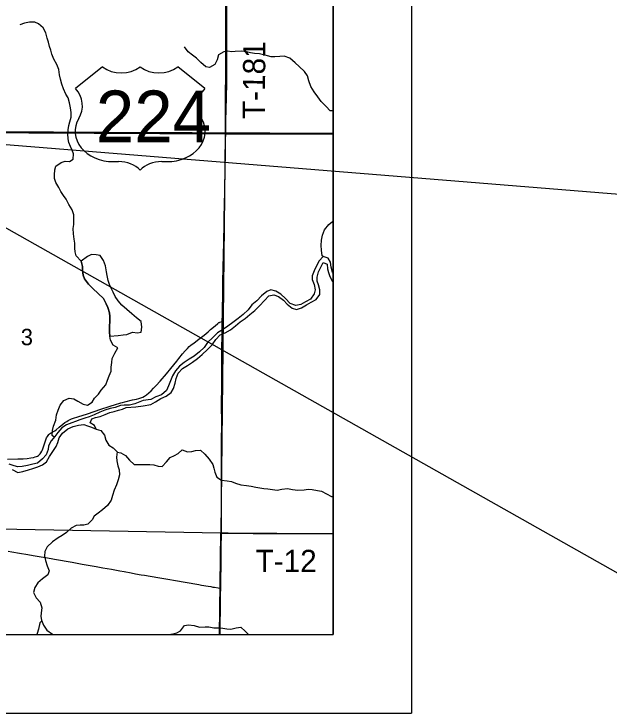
# Model space of a CAD drawing. Extents: x 0 to 34, y 0 to 22.
# Drawn here: x 8.493 to 9.252, y 14 to 14.891 of the extents above; entities that cross this region are included whole.
import ezdxf

# ---------------------------------------------------------------- set-up
doc = ezdxf.new("R2010")
doc.units = 0
for name, color, linetype in [('GM_X_Corporation', 7, 'Continuous'), ('GM_X_County_Road', 7, 'Continuous'), ('GM_X_Major_River', 7, 'Continuous'), ('GM_X_Minor_Lake', 7, 'Continuous'), ('GM_X_Minor_River', 7, 'Continuous'), ('GM_X_Section_Text', 7, 'Continuous'), ('GM_X_Township_Road', 7, 'Continuous'), ('GM_X_Township_Road_Text', 7, 'Continuous'), ('GM_X_US_Location', 7, 'Continuous'), ('GM_X_US_Route', 7, 'Continuous'), ('GM_X_US_Shield', 7, 'Continuous'), ('SH_Data', 7, 'Continuous'), ('SH_Text', 7, 'Continuous')]:
    doc.layers.add(name, color=color, linetype=linetype)

msp = doc.modelspace()

# ---------------------------------------------------------------- linework, layer by layer
at = {"layer": 'GM_X_Corporation'}
for points in [[(2.1, 20.71973), (2.1, 14.1), (8.9, 14.1), (8.9, 20.77204)], [(8.46983, 14.7408), (8.50534, 14.74055), (8.54325, 14.7406), (8.57401, 14.74045), (8.61034, 14.74013), (8.6641, 14.74008), (8.68834, 14.74), (8.72034, 14.73988), (8.76199, 14.73959), (8.76305, 14.73959), (8.79524, 14.73942), (8.81918, 14.73932), (8.86703, 14.73918), (8.89873, 14.73911), (8.9, 14.7391), (8.9, 17.77596)], [(6.729, 14.1), (8.9, 14.1), (8.9, 14.7391), (8.89873, 14.73911), (8.86703, 14.73918), (8.81918, 14.73932), (8.79524, 14.73942), (8.76305, 14.73959), (8.76199, 14.73959), (8.72034, 14.73988), (8.68834, 14.74), (8.6641, 14.74008), (8.61034, 14.74013), (8.57401, 14.74045), (8.54325, 14.7406), (8.50534, 14.74055), (8.46983, 14.7408)]]:
    msp.add_lwpolyline(points, dxfattribs=at)
for points in [[(8.26181, 15.24197), (8.76425, 15.24174), (8.76242, 14.73868), (8.2606, 14.74118)], [(8.9, 14.73823), (8.9, 15.24104), (8.76425, 15.24174), (8.76242, 14.73868)], [(8.2606, 14.74118), (8.76242, 14.73868), (8.75677, 14.2292), (8.25919, 14.2385)], [(8.9, 14.22852), (8.9, 14.73823), (8.76242, 14.73868), (8.75677, 14.2292)], [(8.25754, 14.1), (8.75508, 14.1), (8.75677, 14.2292), (8.25919, 14.2385)], [(8.75508, 14.1), (8.9, 14.1), (8.9, 14.22852), (8.75677, 14.2292)]]:
    msp.add_lwpolyline(points, close=True, dxfattribs=at)
at = {"layer": 'GM_X_County_Road'}
for points in [[(8.75873, 14.49937), (8.75897, 14.50831), (8.75916, 14.51701), (8.75916, 14.52012), (8.75924, 14.52882), (8.75921, 14.53472), (8.75931, 14.53968), (8.75947, 14.54558), (8.75947, 14.55056), (8.75952, 14.55615), (8.75966, 14.56142), (8.75988, 14.57105), (8.76008, 14.58131), (8.76059, 14.60306), (8.76092, 14.62139), (8.7611, 14.63164), (8.76146, 14.64904), (8.76178, 14.66489), (8.7624, 14.69627), (8.76269, 14.71088), (8.76277, 14.71771), (8.76282, 14.72175), (8.76287, 14.72547), (8.76293, 14.73011), (8.76316, 14.73931)], [(8.75757, 14.22962), (8.75761, 14.23733), (8.75766, 14.25162), (8.75778, 14.26561), (8.75777, 14.28457), (8.75775, 14.30135), (8.75779, 14.31875), (8.75781, 14.34082), (8.75794, 14.37438), (8.75785, 14.38775), (8.75785, 14.39707), (8.75792, 14.41354), (8.75794, 14.42442), (8.75804, 14.44182), (8.75802, 14.45053), (8.7581, 14.46885), (8.75839, 14.47786), (8.75854, 14.4875), (8.75866, 14.49682), (8.75873, 14.49937)], [(8.75675, 14.15906), (8.75682, 14.16367), (8.75693, 14.1702), (8.75719, 14.18853), (8.75738, 14.20531), (8.75744, 14.21433), (8.75754, 14.22458), (8.75757, 14.22962)], [(8.7559, 14.1), (8.75609, 14.11305), (8.75618, 14.11988), (8.75624, 14.12547), (8.75647, 14.13913), (8.75655, 14.14503), (8.75663, 14.15093), (8.75675, 14.15906)]]:
    msp.add_lwpolyline(points, dxfattribs=at)
at = {"layer": 'GM_X_Major_River'}
for points in [[(8.9, 14.56088), (8.89935, 14.56216), (8.89768, 14.56843), (8.89695, 14.57507), (8.89394, 14.58021), (8.88731, 14.58214), (8.88235, 14.57685), (8.8791, 14.57023), (8.87603, 14.56398), (8.87334, 14.55754), (8.87351, 14.5528), (8.87614, 14.54652), (8.87724, 14.53969), (8.87608, 14.53438), (8.87111, 14.52795), (8.86503, 14.52438), (8.85875, 14.5208), (8.85248, 14.5195), (8.84548, 14.52239), (8.83925, 14.52868), (8.83359, 14.53402), (8.82716, 14.53785), (8.82053, 14.53978), (8.8154, 14.53772), (8.80873, 14.53206), (8.80282, 14.52582), (8.79634, 14.52035), (8.79157, 14.5143), (8.78528, 14.50826), (8.77881, 14.50317), (8.77196, 14.49789), (8.76586, 14.49337), (8.75901, 14.48847), (8.75274, 14.48489), (8.74645, 14.47904), (8.73997, 14.47243), (8.73538, 14.466), (8.72948, 14.46053), (8.72281, 14.45525), (8.71653, 14.4513), (8.71025, 14.44696), (8.70416, 14.44244), (8.69882, 14.43639), (8.69518, 14.42996), (8.6925, 14.42371), (8.69019, 14.41746), (8.68732, 14.4114), (8.68122, 14.40574), (8.67381, 14.40331), (8.66753, 14.39993), (8.65778, 14.39837)], [(8.65775, 14.39182), (8.66769, 14.39329), (8.67359, 14.39686), (8.68044, 14.40119), (8.68728, 14.404), (8.69337, 14.40891), (8.69624, 14.41383), (8.69836, 14.42046), (8.69972, 14.42671), (8.70241, 14.43353), (8.70813, 14.43919), (8.71441, 14.44334), (8.72069, 14.44729), (8.72716, 14.452), (8.73287, 14.45729), (8.73992, 14.46351), (8.74564, 14.46975), (8.75042, 14.47618), (8.75595, 14.48222), (8.76241, 14.48466), (8.76907, 14.4888), (8.77554, 14.49389), (8.78164, 14.49898), (8.78792, 14.50331), (8.79401, 14.50803), (8.80029, 14.51331), (8.80639, 14.51916), (8.81268, 14.52615), (8.81821, 14.5322), (8.82467, 14.53331), (8.83054, 14.53138), (8.83696, 14.52641), (8.84168, 14.52146), (8.84773, 14.51611), (8.8536, 14.51475), (8.85968, 14.51681), (8.86614, 14.52039), (8.87223, 14.52377), (8.87832, 14.52754), (8.88328, 14.53358), (8.88312, 14.53966), (8.88145, 14.54612), (8.87976, 14.55087), (8.8796, 14.55599), (8.88133, 14.56244), (8.88459, 14.56849), (8.88746, 14.57455), (8.89238, 14.57244), (8.89311, 14.56636), (8.89423, 14.56161), (8.8961, 14.55686), (8.89948, 14.55039), (8.9, 14.54989)], [(8.65778, 14.39837), (8.64695, 14.39428), (8.64049, 14.39279), (8.63346, 14.39263), (8.62871, 14.39208), (8.62206, 14.38964), (8.61579, 14.38834), (8.60895, 14.38609), (8.6023, 14.38365), (8.59526, 14.38007), (8.58899, 14.37764), (8.58348, 14.37595), (8.57701, 14.37389), (8.5715, 14.37183), (8.56675, 14.37014), (8.56009, 14.36751), (8.55381, 14.36375), (8.54904, 14.35769), (8.54485, 14.35278), (8.54046, 14.34711), (8.53682, 14.34067), (8.53642, 14.33593), (8.53411, 14.3293), (8.52916, 14.32401), (8.52306, 14.31872), (8.51679, 14.31723), (8.50995, 14.31555), (8.50311, 14.31444), (8.49799, 14.31389), (8.49325, 14.31543), (8.48661, 14.31717)], [(8.49076, 14.3107), (8.49777, 14.30668), (8.50422, 14.3078), (8.51125, 14.31004), (8.51696, 14.31173), (8.52323, 14.31416), (8.52931, 14.31642), (8.53426, 14.32019), (8.53809, 14.327), (8.54344, 14.33495), (8.54669, 14.33987), (8.5488, 14.34498), (8.55034, 14.35086), (8.55473, 14.3571), (8.56178, 14.36257), (8.56825, 14.36539), (8.57509, 14.36726), (8.58192, 14.3678), (8.58666, 14.36645), (8.59159, 14.36434), (8.59765, 14.36185), (8.59577, 14.3666), (8.59009, 14.37023), (8.59201, 14.37535), (8.59695, 14.37684), (8.60284, 14.37834), (8.60931, 14.38059), (8.61539, 14.3834), (8.62052, 14.38452), (8.62641, 14.38639), (8.63135, 14.3877), (8.63611, 14.38958), (8.64826, 14.39066), (8.65775, 14.39182)]]:
    msp.add_lwpolyline(points, dxfattribs=at)
at = {"layer": 'GM_X_Minor_Lake'}
for points in [[(8.61506, 14.48075), (8.62588, 14.48146), (8.63233, 14.48219), (8.63708, 14.48274), (8.64412, 14.48556), (8.65037, 14.48477), (8.65531, 14.4857), (8.6561, 14.49215), (8.65499, 14.49917), (8.64913, 14.50394), (8.64308, 14.50928), (8.63703, 14.51443), (8.6306, 14.52015), (8.62569, 14.52567), (8.62211, 14.531), (8.61928, 14.53689), (8.61703, 14.54184), (8.61477, 14.54659), (8.61309, 14.55153), (8.6116, 14.55799), (8.61086, 14.56274), (8.60956, 14.57033), (8.60712, 14.57699), (8.60297, 14.58327), (8.59766, 14.58443), (8.59197, 14.58464), (8.58665, 14.58239), (8.57846, 14.57635)], [(8.57846, 14.57635), (8.58014, 14.56951), (8.58012, 14.56458), (8.58104, 14.5585), (8.58292, 14.55375), (8.58782, 14.54709), (8.59368, 14.54137), (8.60049, 14.53508), (8.60691, 14.5286), (8.61068, 14.52194), (8.61275, 14.517), (8.61462, 14.51054), (8.61516, 14.5056), (8.61514, 14.50048), (8.61473, 14.49194), (8.61489, 14.48549), (8.61506, 14.48075)]]:
    msp.add_lwpolyline(points, dxfattribs=at)
at = {"layer": 'GM_X_Minor_River'}
for points in [[(8.52434, 14.87907), (8.51941, 14.88118), (8.51277, 14.88102), (8.50631, 14.87972), (8.50023, 14.87785)], [(8.5442, 14.35194), (8.54162, 14.35393), (8.54222, 14.36038), (8.54319, 14.36569), (8.54607, 14.37346), (8.54724, 14.38009), (8.54917, 14.38634), (8.55166, 14.39259), (8.55643, 14.39865), (8.56309, 14.40146), (8.56935, 14.40087), (8.57446, 14.39781), (8.58128, 14.39399), (8.58658, 14.39245), (8.59248, 14.39622), (8.59554, 14.4017), (8.60069, 14.40643), (8.60413, 14.41153), (8.61023, 14.41834), (8.61235, 14.42459), (8.61446, 14.4299), (8.61676, 14.43615), (8.61697, 14.44089), (8.61776, 14.44696), (8.61816, 14.45227), (8.62161, 14.45909), (8.62543, 14.46571), (8.61937, 14.46915), (8.61598, 14.47543), (8.61506, 14.48075), (8.61489, 14.48549), (8.61473, 14.49194), (8.61514, 14.50048), (8.61516, 14.5056), (8.61462, 14.51054), (8.61275, 14.517), (8.61068, 14.52194), (8.60691, 14.5286), (8.60049, 14.53508), (8.59368, 14.54137), (8.58782, 14.54709), (8.58292, 14.55375), (8.58104, 14.5585), (8.58012, 14.56458), (8.58014, 14.56951), (8.57846, 14.57635), (8.57242, 14.58321), (8.57092, 14.58815), (8.57056, 14.59289), (8.5704, 14.59934), (8.56947, 14.60447), (8.56874, 14.61112), (8.56858, 14.61776), (8.56917, 14.62288), (8.56939, 14.62876), (8.56922, 14.63522), (8.56716, 14.64168), (8.56283, 14.64834), (8.55944, 14.65537), (8.55624, 14.66013), (8.55284, 14.66508), (8.55021, 14.67021), (8.54625, 14.67649), (8.54475, 14.68162), (8.54477, 14.68656), (8.54499, 14.69263), (8.54634, 14.69737), (8.553, 14.70208), (8.55813, 14.70377), (8.56363, 14.70355), (8.56839, 14.70619), (8.56899, 14.71302), (8.5673, 14.71777), (8.56504, 14.72253), (8.56298, 14.72747), (8.56186, 14.73222), (8.56151, 14.73848), (8.56191, 14.7436), (8.56269, 14.74929), (8.56404, 14.75403), (8.56577, 14.75972), (8.5658, 14.76598), (8.56487, 14.77187), (8.56376, 14.77832), (8.56208, 14.78459), (8.55907, 14.78935), (8.55587, 14.79582), (8.5538, 14.8019), (8.55231, 14.80817), (8.55101, 14.81406), (8.55009, 14.8207), (8.54765, 14.82697), (8.54369, 14.83382), (8.54106, 14.84029), (8.53976, 14.84523), (8.53807, 14.84998), (8.53676, 14.85568), (8.53527, 14.86062), (8.5334, 14.86746), (8.53001, 14.87373), (8.52434, 14.87907)], [(8.9, 14.76787), (8.89656, 14.76788), (8.89108, 14.77342), (8.88504, 14.77971), (8.88052, 14.78599), (8.87581, 14.79228), (8.87167, 14.79913), (8.86905, 14.80636), (8.86737, 14.81244), (8.86342, 14.81834), (8.85681, 14.82464), (8.85152, 14.82903), (8.84472, 14.83513), (8.83771, 14.83764), (8.83221, 14.83728), (8.82595, 14.83674), (8.82121, 14.83696), (8.81628, 14.83793), (8.81136, 14.83928), (8.80624, 14.84045), (8.7996, 14.84105), (8.79468, 14.84183), (8.78956, 14.843), (8.7835, 14.84398), (8.77534, 14.84364), (8.7704, 14.84309), (8.76567, 14.84407), (8.76054, 14.84333), (8.75389, 14.83957), (8.75196, 14.83313), (8.74908, 14.82707), (8.74243, 14.82331), (8.7375, 14.82428), (8.73127, 14.82962), (8.7256, 14.83534), (8.72069, 14.83916), (8.71502, 14.84337), (8.7105, 14.84965)], [(8.88726, 14.58209), (8.88618, 14.5831), (8.88526, 14.59012), (8.88491, 14.59639), (8.88552, 14.60322), (8.88668, 14.60928), (8.88918, 14.61629), (8.89453, 14.62291), (8.89929, 14.62668), (8.9, 14.62751)], [(8.59765, 14.36185), (8.60371, 14.3605), (8.60824, 14.35441), (8.61011, 14.34776), (8.61388, 14.34167), (8.61956, 14.33823), (8.62447, 14.33289), (8.62387, 14.32645), (8.62404, 14.3217), (8.62553, 14.31506), (8.62722, 14.31012), (8.62757, 14.30366), (8.62602, 14.29741), (8.62353, 14.29116), (8.62065, 14.28434), (8.61872, 14.27752), (8.61699, 14.27145), (8.61202, 14.26464), (8.60574, 14.25898), (8.60021, 14.25502), (8.59526, 14.25125), (8.59277, 14.24632), (8.58706, 14.24066), (8.58212, 14.23954), (8.57718, 14.23937), (8.57225, 14.23901), (8.56578, 14.23581), (8.56006, 14.23015), (8.55435, 14.22657), (8.54921, 14.22355), (8.54198, 14.21827), (8.53531, 14.21204), (8.53205, 14.20617), (8.53165, 14.19991), (8.53295, 14.19459), (8.53539, 14.18756), (8.53764, 14.18148), (8.5361, 14.17637), (8.52924, 14.17127), (8.52315, 14.16599), (8.51951, 14.15993), (8.51778, 14.15349), (8.52117, 14.14702), (8.52626, 14.14131), (8.52832, 14.13428), (8.52753, 14.12783), (8.52732, 14.12309), (8.52806, 14.11834), (8.5305, 14.11207), (8.53465, 14.10579), (8.54203, 14.10045), (8.54297, 14.1)], [(8.65732, 14.3168), (8.66618, 14.31683), (8.6713, 14.31642), (8.67679, 14.31488), (8.68191, 14.31447), (8.68744, 14.32013), (8.69221, 14.3258), (8.69753, 14.32843), (8.70228, 14.33088), (8.70762, 14.33559), (8.71444, 14.33328), (8.71994, 14.33345), (8.72469, 14.33494), (8.73076, 14.3351), (8.73642, 14.32995), (8.74208, 14.32385), (8.74679, 14.31699), (8.74809, 14.31224), (8.74921, 14.30712), (8.75164, 14.30084), (8.75788, 14.29702), (8.76508, 14.29622), (8.77039, 14.29506), (8.77569, 14.29332), (8.78232, 14.29101), (8.78952, 14.29003), (8.79559, 14.28943), (8.80165, 14.28807), (8.80658, 14.2871), (8.81189, 14.2865), (8.817, 14.28591), (8.82288, 14.28493), (8.82895, 14.28414), (8.83483, 14.28544), (8.84204, 14.28616), (8.84849, 14.28518), (8.85531, 14.2842), (8.86309, 14.28473), (8.86821, 14.28528), (8.87352, 14.28487), (8.88016, 14.28389), (8.88527, 14.28272), (8.89814, 14.27621), (8.9, 14.27626)], [(8.62445, 14.33272), (8.62902, 14.33193), (8.63508, 14.3283), (8.64018, 14.32239), (8.64604, 14.31687), (8.65732, 14.3168)], [(8.52829, 14.11775), (8.52596, 14.11494), (8.52402, 14.10679), (8.52229, 14.10148), (8.52196, 14.1)], [(8.6903, 14.1), (8.69564, 14.10114), (8.70077, 14.10225), (8.70552, 14.1047), (8.71068, 14.11169), (8.71562, 14.11243), (8.72282, 14.11182), (8.72945, 14.1097), (8.73666, 14.10986), (8.7414, 14.11002), (8.74803, 14.10885), (8.75448, 14.10863), (8.7596, 14.10822), (8.76453, 14.10725), (8.76965, 14.10704), (8.77629, 14.10871), (8.78237, 14.10944), (8.78803, 14.10448), (8.79207, 14.1)]]:
    msp.add_lwpolyline(points, dxfattribs=at)
at = {"layer": 'GM_X_Township_Road'}
for points in [[(8.76316, 14.73931), (8.76319, 14.74156), (8.76338, 14.7562), (8.76366, 14.76944), (8.76438, 14.80225), (8.7644, 14.81965), (8.76439, 14.82772), (8.76441, 14.84077), (8.7645, 14.85849), (8.76441, 14.88428), (8.7643, 14.89701), (8.76437, 14.93298), (8.76428, 14.95317), (8.76405, 14.99138), (8.76431, 15.0237), (8.76431, 15.04391), (8.76436, 15.06224), (8.76442, 15.10047), (8.76457, 15.12067), (8.76451, 15.14771), (8.76471, 15.16853), (8.76478, 15.20303), (8.76501, 15.2313), (8.765, 15.24037)], [(8.75873, 14.49937), (8.75897, 14.50831), (8.75916, 14.51701), (8.75916, 14.52012), (8.75924, 14.52882), (8.75921, 14.53472), (8.75931, 14.53968), (8.75947, 14.54558), (8.75947, 14.55056), (8.75952, 14.55615), (8.75966, 14.56142), (8.75988, 14.57105), (8.76008, 14.58131), (8.76059, 14.60306), (8.76092, 14.62139), (8.7611, 14.63164), (8.76146, 14.64904), (8.76178, 14.66489), (8.7624, 14.69627), (8.76269, 14.71088), (8.76277, 14.71771), (8.76282, 14.72175), (8.76287, 14.72547), (8.76293, 14.73011), (8.76316, 14.73931)], [(8.54208, 14.3584), (8.54335, 14.35899), (8.54498, 14.35989), (8.54672, 14.36118), (8.55053, 14.36438), (8.55524, 14.36846), (8.55792, 14.37051), (8.56011, 14.37196), (8.56218, 14.37308), (8.56381, 14.37389), (8.56644, 14.37498), (8.56898, 14.37594), (8.57428, 14.37774), (8.58672, 14.38173), (8.60351, 14.38741), (8.61445, 14.39096), (8.62365, 14.3938), (8.62669, 14.39479), (8.62917, 14.39551), (8.63137, 14.39616), (8.63454, 14.39697), (8.64431, 14.39922), (8.6492, 14.40035), (8.65216, 14.40105), (8.65495, 14.40196), (8.65715, 14.40288), (8.6593, 14.40411), (8.66184, 14.4059), (8.66499, 14.40843), (8.66777, 14.41092), (8.67106, 14.41422), (8.67445, 14.41785), (8.67944, 14.42339), (8.6874, 14.43254), (8.69316, 14.43947), (8.70074, 14.44893), (8.70324, 14.45212), (8.7081, 14.45818), (8.71135, 14.46193), (8.71415, 14.46485), (8.71663, 14.46721), (8.71872, 14.46906), (8.72261, 14.47215), (8.72856, 14.47666), (8.73202, 14.4793), (8.73543, 14.48201), (8.74048, 14.48614), (8.74381, 14.48892), (8.74945, 14.49375), (8.7532, 14.49696), (8.75443, 14.49788), (8.75511, 14.4982), (8.75578, 14.49848), (8.75873, 14.49937)], [(8.75757, 14.22962), (8.75761, 14.23733), (8.75766, 14.25162), (8.75778, 14.26561), (8.75777, 14.28457), (8.75775, 14.30135), (8.75779, 14.31875), (8.75781, 14.34082), (8.75794, 14.37438), (8.75785, 14.38775), (8.75785, 14.39707), (8.75792, 14.41354), (8.75794, 14.42442), (8.75804, 14.44182), (8.75802, 14.45053), (8.7581, 14.46885), (8.75839, 14.47786), (8.75854, 14.4875), (8.75866, 14.49682), (8.75873, 14.49937)], [(8.4846, 14.3237), (8.49797, 14.32404), (8.50449, 14.32432), (8.50976, 14.32478), (8.51435, 14.32534), (8.51762, 14.32593), (8.52004, 14.32658), (8.52151, 14.32708), (8.52283, 14.32766), (8.52401, 14.32835), (8.52503, 14.32916), (8.52621, 14.3305), (8.52708, 14.33168), (8.52833, 14.33383), (8.52915, 14.33584), (8.53307, 14.34701), (8.53456, 14.35077), (8.53555, 14.35272), (8.53638, 14.35401), (8.53738, 14.35527), (8.53839, 14.35614), (8.53932, 14.35682), (8.54039, 14.35752), (8.54165, 14.3582), (8.54208, 14.3584)], [(8.75675, 14.15906), (8.75682, 14.16367), (8.75693, 14.1702), (8.75719, 14.18853), (8.75738, 14.20531), (8.75744, 14.21433), (8.75754, 14.22458), (8.75757, 14.22962)], [(8.75757, 14.22962), (8.76107, 14.22961), (8.76635, 14.2296), (8.77972, 14.22938), (8.79805, 14.22911), (8.81733, 14.22902), (8.83349, 14.22905), (8.85805, 14.22905), (8.87235, 14.22895), (8.88789, 14.22883), (8.9, 14.22881)], [(8.48548, 14.20651), (8.49022, 14.20575), (8.50001, 14.20401), (8.51041, 14.20217), (8.51715, 14.20106), (8.52512, 14.19979), (8.5331, 14.19851), (8.5336, 14.19842)], [(8.5336, 14.19842), (8.54472, 14.19641), (8.56703, 14.19226), (8.5799, 14.1899), (8.59786, 14.18665), (8.60642, 14.18513), (8.61714, 14.18325), (8.62783, 14.18137), (8.63364, 14.18032), (8.64221, 14.17876), (8.64801, 14.17766), (8.65504, 14.17639), (8.65933, 14.17566), (8.6765, 14.17276), (8.69182, 14.17013), (8.69641, 14.16933), (8.72889, 14.16378), (8.73226, 14.1632), (8.74084, 14.16175), (8.74421, 14.16117), (8.74665, 14.1607), (8.74878, 14.16036), (8.75358, 14.15957), (8.75675, 14.15906)], [(8.7559, 14.1), (8.75609, 14.11305), (8.75618, 14.11988), (8.75624, 14.12547), (8.75647, 14.13913), (8.75655, 14.14503), (8.75663, 14.15093), (8.75675, 14.15906)]]:
    msp.add_lwpolyline(points, dxfattribs=at)
at = {"layer": 'GM_X_US_Route'}
msp.add_lwpolyline([(8.26169, 14.7416), (8.27394, 14.7415), (8.32646, 14.7413), (8.3678, 14.74106), (8.42436, 14.74084), (8.46994, 14.74052), (8.50545, 14.74028), (8.54336, 14.74033), (8.57412, 14.74018), (8.61045, 14.73986), (8.66421, 14.73981), (8.68845, 14.73973), (8.72045, 14.73961), (8.7621, 14.73932), (8.76316, 14.73931), (8.79535, 14.73914), (8.81929, 14.73904), (8.86714, 14.73891), (8.89884, 14.73883), (8.9, 14.73883)], dxfattribs=at)
at = {"layer": 'GM_X_US_Shield'}
for p, q in [((8.60582, 14.82409), (8.57149, 14.79662)), ((8.73629, 14.79662), (8.70195, 14.82409)), ((8.61956, 14.70324), (8.62642, 14.70324)), ((8.68136, 14.70324), (8.68822, 14.70324))]:
    msp.add_line(p, q, dxfattribs=at)
for centre, major_axis, start_param, end_param in [((8.62986, 14.8437), (-0.03433, 0), 0.795399, 2.346194), ((8.67792, 14.8437), (-0.03433, 0), 0.795399, 2.346194), ((8.53212, 14.77456), (0.04807, 0), 5.838949, 6.894067), ((8.77566, 14.77456), (-0.04807, 0), 5.672304, 6.727422), ((8.61902, 14.74169), (0.04807, 0), 2.702327, 4.723529), ((8.68876, 14.74169), (-0.04807, 0), 1.559657, 3.580859), ((8.62642, 14.67577), (-0.03433, 0), 3.785094, 4.712389), ((8.68136, 14.67577), (-0.03433, 0), 4.712389, 5.639684)]:
    msp.add_ellipse(centre, major_axis=major_axis, ratio=0.8, start_param=start_param, end_param=end_param, dxfattribs=at)
at = {"layer": 'SH_Data'}
for p, q in [((9, 21), (9, 14)), ((8.9, 20.9), (8.9, 14.1)), ((2.1, 14.1), (8.9, 14.1)), ((2, 14), (9, 14))]:
    msp.add_line(p, q, dxfattribs=at)
at = {"layer": 'SH_Text'}
msp.add_lwpolyline([(9.29702, 14.15908), (8.26168, 14.74269), (9.29702, 14.65908)], close=True, dxfattribs=at)

# ---------------------------------------------------------------- texts
at = {"layer": 'GM_X_Section_Text'}
msp.add_text('3', height=0.02093, rotation=0.00001, dxfattribs=at).set_placement((8.50152, 14.46905))
at = {"layer": 'GM_X_Township_Road_Text'}
for s, rotation, p in [('T-181', 89.44385, (8.8129, 14.75732)), ('T-12', 0.00001, (8.8011, 14.17971))]:
    msp.add_text(s, height=0.028409, rotation=rotation, dxfattribs=at).set_placement(p)
at = {"layer": 'GM_X_US_Location'}
for s, p in [('0', (8.64439, 14.74001)), ('/', (8.6444, 14.74001))]:
    msp.add_text(s, height=0.0000947, dxfattribs=at).set_placement(p)
msp.add_text('224', height=0.0000947, rotation=0.00001, dxfattribs=at).set_placement((8.61526, 14.72041))
at = {"layer": 'GM_X_US_Shield'}
msp.add_text('224', height=0.065918, dxfattribs=at).set_placement((8.59731, 14.72795))

doc.saveas('drawing.dxf')
